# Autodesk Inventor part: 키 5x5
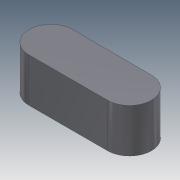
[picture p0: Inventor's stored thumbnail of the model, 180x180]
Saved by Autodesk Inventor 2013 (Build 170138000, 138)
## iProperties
Company: 한국ATC센터
Created: 2014-10
Part Number: 키 5x5
Document SubType Name: Modeling
Designer: KYOUNG IL JANG
Density: 7.85 g/cm^3
Mass: 2.53692 g
Surface Area: 2.9781 cm^2
Volume: 0.323175 cm^3
Material: 강철
Author: KYOUNG IL JANG
Revision Number: 1
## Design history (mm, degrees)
sketch "스케치1"
  geometry: L1 (-4.5, -2.5)-(4.5, -2.5); L2 (4.5, 2.5)-(-4.5, 2.5); A1 r 2.5 centre (4.5, 0) between (4.5, -2.5) and (4.5, 2.5); A2 r 2.5 centre (-4.5, 0) between (-4.5, 2.5) and (-4.5, -2.5); 2 further points
  constraints: 4 end point, 4 point on circle, 4 tangent, 2 centre point, 1 horizontal, 1 horizontal alignment, 1 midpoint, 1 parallel, 1 vertical alignment
  dimensions: "d0" = 5 distance between parallel lines of L1 L2; "d1" = 14 dimension on A1 A2
extrude "돌출1" new body sketch "스케치1" stored distance "d2" = 5; taper "d3" = 0 deg
node "솔리드1"
